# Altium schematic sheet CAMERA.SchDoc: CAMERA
size A4; Author: Daniela Catanzaro; CompanyName: Arduino srl; DocumentNumber: ASX00055; SheetNumber: 4; SheetTotal: 10; RevAuthor: Daniela Catanzaro
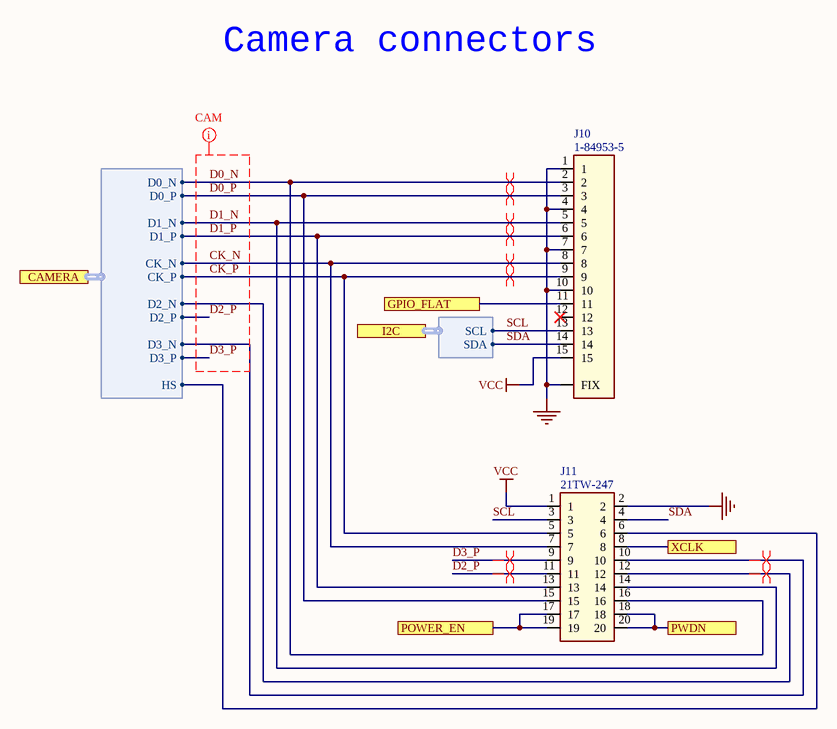
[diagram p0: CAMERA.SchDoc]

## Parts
J10  1-84953-5  [1-84952-5-Footprint-1]
J11  21TW-247  [21TW-247]

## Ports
CAMERA (harness CAMERA), GPIO_FLAT, I2C (harness I2C), POWER_EN, PWDN, XCLK

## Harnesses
I2C: SDA, SCL
CAMERA: D3_P, D3_N, D2_P, D2_N, D1_P, D1_N, D0_P, D0_N, CK_P, CK_N, HS

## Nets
GND: J10.1 J10.4 J10.7 J10.10 J10.FIX J11.2
VCC: J10.15 J11.1
CK_N: J10.8 J11.7 ; port CAMERA.CK_N
CK_P: J10.9 J11.5 ; port CAMERA.CK_P
D0_N: J10.2 J11.16 ; port CAMERA.D0_N
D0_P: J10.3 J11.15 ; port CAMERA.D0_P
D1_N: J10.5 J11.14 ; port CAMERA.D1_N
D1_P: J10.6 J11.13 ; port CAMERA.D1_P
D2_P: J11.11 ; port CAMERA.D2_P
D3_P: J11.9 ; port CAMERA.D3_P
GPIO_FLAT: J10.11 ; port GPIO_FLAT
POWER_EN: J11.17 J11.19 ; port POWER_EN
PWDN: J11.18 J11.20 ; port PWDN
SCL: J10.13 J11.3 ; port I2C.SCL
SDA: J10.14 J11.4 ; port I2C.SDA
XCLK: J11.8 ; port XCLK
NetJ11_6: J11.6 ; port CAMERA.HS
NetJ11_10: J11.10 ; port CAMERA.D3_N
NetJ11_12: J11.12 ; port CAMERA.D2_N

Not connected (* = marked no-connect by the designer): J10 12*

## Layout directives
differential pair; differential pair class CAMERA; net class DIFFERENTIAL: CK_N, CK_P, D0_N, D0_P, D1_N, D1_P, D2_P, D3_P, NetJ11_10, NetJ11_12
net class CAM; net class DIFFERENTIAL: CK_N, CK_P, D0_N, D0_P, D1_N, D1_P, D2_P, D3_P

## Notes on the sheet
- Camera connectors

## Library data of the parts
J10 = J0320-A.3: CONN FFC/FPC Connector, 15 Contact(s), 1 Row(s), TOP CONTACT, Female, Right Angle, 1mm Pitch, Locking ZIF; Manufacturer: TE Connectivity; Number of Contacts: 15; Insulation Resistance: 1GR; Connector Type: CARD EDGE CONNECTOR; Contact Resistance: 10mR; Code Arduino: J0320
J11 = J0249-A.9: CONN SOCKET 2ROW 20POS VERTICAL PASS THROUGH + SMD with fixing + pick and place cap, in reel; Manufacturer: 4UCON; Connector Type: BOARD CONNECTOR; Code Arduino: J0249; Number of Contacts: 20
